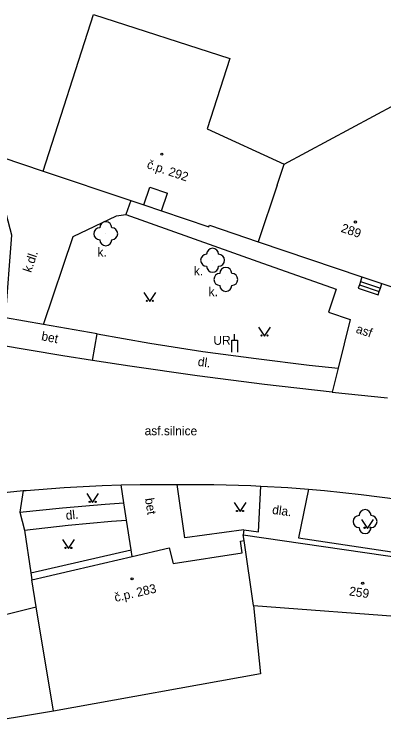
# Model space of a CAD drawing. Extents: x -544674 to -541478, y -1199076 to -1195527.
# Drawn here: x -542914.6 to -542883.7, y -1198202.9 to -1198142.3 of the extents above; entities that cross this region are included whole.
import ezdxf

# ---------------------------------------------------------------- set-up
doc = ezdxf.new("R2010")
doc.units = 0
for name, color, linetype in [('BUDOVY_MĚŘ', 7, 'Continuous'), ('BUDOVY_NEMĚŘ', 7, 'Continuous'), ('POMOC_POPIS', 7, 'Continuous'), ('ROZHRANÍ_PLOCH', 7, 'Continuous'), ('ZELEŇ', 7, 'Continuous'), ('ZN_BUDOV', 7, 'Continuous'), ('ZN_DOPLŇKOVÉ', 7, 'Continuous'), ('ZN_KULTUR', 7, 'Continuous'), ('Č_POPIS_ORIENT', 7, 'Continuous')]:
    doc.layers.add(name, color=color, linetype=linetype)

msp = doc.modelspace()

# ---------------------------------------------------------------- linework, layer by layer
at = {"layer": 'BUDOVY_MĚŘ'}
for points in [[(-542912.2, -1198155.37), (-542904.87, -1198157.84)], [(-542892.61, -1198156.55), (-542894.21, -1198161.29)], [(-542904.87, -1198157.84), (-542903.78, -1198158.21)], [(-542903.78, -1198158.21), (-542902.3, -1198158.71)], [(-542902.3, -1198158.71), (-542898.34, -1198160.05), (-542898.29, -1198159.91), (-542894.21, -1198161.29)], [(-542894.21, -1198161.29), (-542885.51, -1198164.23)], [(-542885.51, -1198164.23), (-542883.84, -1198164.79)], [(-542883.84, -1198164.79), (-542881.19, -1198165.68)], [(-542904.75, -1198187.64), (-542901.64, -1198186.92), (-542901.33, -1198188.23), (-542895.54, -1198187.34), (-542895.68, -1198186.36), (-542895.38, -1198186.32)], [(-542895.45, -1198185.83), (-542880.28, -1198188.03)], [(-542895.38, -1198186.32), (-542895.45, -1198185.83)], [(-542894.6, -1198191.76), (-542895.38, -1198186.32)], [(-542913.14, -1198189.59), (-542904.75, -1198187.64)], [(-542912.78, -1198191.87), (-542913.14, -1198189.59)], [(-542927.63, -1198193.04), (-542918.98, -1198191.04), (-542918.44, -1198193.25), (-542912.78, -1198191.87)]]:
    msp.add_lwpolyline(points, dxfattribs=at)
at = {"layer": 'BUDOVY_NEMĚŘ'}
for points in [[(-542912.2, -1198155.37), (-542908, -1198142.26), (-542896.58, -1198145.94), (-542898.48, -1198151.84), (-542892.02, -1198154.79)], [(-542892.61, -1198156.55), (-542892.02, -1198154.79), (-542882.67, -1198149.76)], [(-542894.6, -1198191.76), (-542894, -1198197.47), (-542911.34, -1198200.59), (-542912.78, -1198191.87)], [(-542894.6, -1198191.76), (-542881.22, -1198192.76)], [(-542911.34, -1198200.59), (-542925.16, -1198202.89), (-542927.63, -1198193.04)]]:
    msp.add_lwpolyline(points, dxfattribs=at)
at = {"layer": 'ROZHRANÍ_PLOCH'}
for points in [[(-542915.37, -1198167.65), (-542914.83, -1198160.74), (-542916.05, -1198156.17), (-542915.67, -1198154.2), (-542912.2, -1198155.37)], [(-542903.78, -1198158.21), (-542903.27, -1198156.72)], [(-542903.27, -1198156.72), (-542901.79, -1198157.22)], [(-542902.3, -1198158.71), (-542901.79, -1198157.22)], [(-542904.87, -1198157.84), (-542905.27, -1198159.02)], [(-542912.17, -1198168.22), (-542909.7, -1198160.84), (-542906.07, -1198159.12), (-542905.27, -1198159.02)], [(-542905.27, -1198159.02), (-542894.22, -1198162.94), (-542887.68, -1198165.27), (-542888.32, -1198167.18), (-542886.49, -1198167.79), (-542887.51, -1198171.87)], [(-542885.51, -1198164.23), (-542885.64, -1198164.62)], [(-542885.73, -1198164.9), (-542885.83, -1198165.19), (-542884.16, -1198165.75), (-542884.07, -1198165.47)], [(-542885.64, -1198164.62), (-542885.73, -1198164.9)], [(-542885.73, -1198164.9), (-542884.07, -1198165.47)], [(-542885.64, -1198164.62), (-542883.97, -1198165.18)], [(-542884.07, -1198165.47), (-542883.97, -1198165.18)], [(-542883.97, -1198165.18), (-542883.84, -1198164.79)], [(-542912.17, -1198168.22), (-542915.37, -1198167.65)], [(-542907.69, -1198169.01), (-542912.17, -1198168.22)], [(-542908.06, -1198171.24), (-542907.69, -1198169.01)], [(-542907.69, -1198169.01), (-542903.27, -1198169.78), (-542898.83, -1198170.47), (-542894.38, -1198171.08), (-542889.92, -1198171.62), (-542887.51, -1198171.87)], [(-542908.06, -1198171.24), (-542910.57, -1198170.85), (-542916.06, -1198169.91)], [(-542888.01, -1198173.88), (-542893.66, -1198173.24), (-542899.31, -1198172.52), (-542904.94, -1198171.72), (-542908.06, -1198171.24)], [(-542887.51, -1198171.87), (-542888.01, -1198173.88)], [(-542888.01, -1198173.88), (-542883.38, -1198174.36)], [(-542918.92, -1198182.7), (-542916.81, -1198182.43), (-542913.87, -1198182.13)], [(-542913.87, -1198182.13), (-542914.16, -1198183.94)], [(-542913.87, -1198182.13), (-542913.63, -1198182.11), (-542910.45, -1198181.86), (-542907.27, -1198181.7), (-542905.67, -1198181.66)], [(-542905.67, -1198181.66), (-542904.08, -1198181.62), (-542900.99, -1198181.61)], [(-542905.44, -1198183.16), (-542905.67, -1198181.66)], [(-542900.99, -1198181.61), (-542897.9, -1198181.62), (-542894.81, -1198181.71), (-542893.99, -1198181.75)], [(-542895.39, -1198185.41), (-542900.34, -1198186.09), (-542900.99, -1198181.61)], [(-542895.39, -1198185.41), (-542894.18, -1198185.59), (-542893.99, -1198181.75)], [(-542893.99, -1198181.75), (-542891.72, -1198181.88), (-542889.98, -1198182.02)], [(-542889.98, -1198182.02), (-542890.83, -1198186.09), (-542880.23, -1198187.67), (-542879.45, -1198183.34)], [(-542889.98, -1198182.02), (-542888.64, -1198182.12), (-542885.57, -1198182.45), (-542882.5, -1198182.86), (-542879.45, -1198183.34)], [(-542914.16, -1198183.94), (-542910.59, -1198183.56), (-542907.02, -1198183.27), (-542905.44, -1198183.16)], [(-542905.22, -1198184.6), (-542905.44, -1198183.16)], [(-542914.16, -1198183.94), (-542913.76, -1198185.45)], [(-542913.76, -1198185.45), (-542910.12, -1198185.03), (-542906.47, -1198184.7), (-542905.22, -1198184.6)], [(-542904.84, -1198187.08), (-542905.22, -1198184.6)], [(-542913.76, -1198185.45), (-542913.23, -1198189.02)], [(-542895.39, -1198185.41), (-542895.45, -1198185.83)], [(-542913.23, -1198189.02), (-542904.84, -1198187.08)], [(-542904.75, -1198187.64), (-542904.84, -1198187.08)], [(-542913.23, -1198189.02), (-542913.14, -1198189.59)]]:
    msp.add_lwpolyline(points, dxfattribs=at)
at = {"layer": 'ZELEŇ'}
for centre in [(-542906.96, -1198160.62), (-542898.02, -1198162.84), (-542896.91, -1198164.45), (-542885.25, -1198184.72)]:
    msp.add_circle(centre, 0.0005, dxfattribs=at)
for centre, start, end in [((-542906.96, -1198160.12), 0, 179.99999), ((-542907.46, -1198160.62), 89.99999, 269.99999), ((-542906.46, -1198160.62), 270, 89.99999), ((-542906.96, -1198161.12), 179.99999, 359.99999), ((-542898.02, -1198162.34), 0, 179.99999), ((-542898.52, -1198162.84), 89.99999, 269.99999), ((-542897.52, -1198162.84), 270, 89.99999), ((-542898.02, -1198163.34), 179.99999, 359.99999), ((-542897.41, -1198164.45), 89.99999, 269.99999), ((-542896.91, -1198163.95), 0, 179.99999), ((-542896.41, -1198164.45), 270, 89.99999), ((-542896.91, -1198164.95), 179.99999, 359.99999), ((-542885.25, -1198184.22), 0, 179.99999), ((-542885.75, -1198184.72), 89.99999, 269.99999), ((-542884.75, -1198184.72), 270, 89.99999), ((-542885.25, -1198185.22), 179.99999, 359.99999)]:
    msp.add_arc(centre, 0.5, start, end, dxfattribs=at)
at = {"layer": 'ZN_BUDOV'}
for centre in [(-542902.27, -1198153.95), (-542886.06, -1198159.64), (-542904.76, -1198189.52), (-542885.45, -1198189.89)]:
    msp.add_circle(centre, 0.0875, dxfattribs=at)
at = {"layer": 'ZN_DOPLŇKOVÉ'}
msp.add_line((-542896.17, -1198169.54), (-542896.17, -1198169.04), dxfattribs=at)
msp.add_lwpolyline([(-542896.42, -1198170.54), (-542896.42, -1198169.54), (-542895.92, -1198169.54), (-542895.92, -1198170.54)], dxfattribs=at)
at = {"layer": 'ZN_KULTUR'}
for points in [[(-542903.77, -1198165.54), (-542903.27, -1198166.29), (-542902.77, -1198165.54)], [(-542894.17, -1198168.44), (-542893.67, -1198169.19), (-542893.17, -1198168.44)], [(-542908.56, -1198182.37), (-542908.06, -1198183.12), (-542907.56, -1198182.37)], [(-542896.22, -1198183.14), (-542895.72, -1198183.89), (-542895.22, -1198183.14)], [(-542885.54, -1198184.54), (-542885.04, -1198185.29), (-542884.54, -1198184.54)], [(-542910.59, -1198186.23), (-542910.09, -1198186.98), (-542909.59, -1198186.23)]]:
    msp.add_lwpolyline(points, dxfattribs=at)
for centre in [(-542903.52, -1198166.24), (-542903.02, -1198166.24), (-542893.92, -1198169.14), (-542893.42, -1198169.14), (-542908.31, -1198183.07), (-542907.81, -1198183.07), (-542895.97, -1198183.84), (-542895.47, -1198183.84), (-542885.29, -1198185.24), (-542884.79, -1198185.24), (-542910.34, -1198186.93), (-542909.84, -1198186.93)]:
    msp.add_circle(centre, 0.05, dxfattribs=at)

# ---------------------------------------------------------------- texts
at = {"layer": 'POMOC_POPIS'}
for s, rotation, p in [('k.dl.', 71.49521, (-542913.21, -1198163.92)), ('bet', 349.03002, (-542912.4, -1198169.53)), ('asf', 341.36, (-542886.07, -1198168.89)), ('dl.', 352.37999, (-542899.29, -1198171.68)), ('asf.silnice', 359.81458, (-542903.71, -1198177.49)), ('bet', 278.68999, (-542903.68, -1198182.8)), ('dla.', 352.69001, (-542893.06, -1198184.08)), ('dl.', 5.34999, (-542910.28, -1198184.58))]:
    msp.add_text(s, height=0.75, rotation=rotation, dxfattribs=at).set_placement(p)
msp.add_text('UR', height=0.75, dxfattribs=at).set_placement((-542897.95, -1198169.92))
at = {"layer": 'ZELEŇ'}
for p in [(-542907.66, -1198162.53), (-542899.59, -1198164.1), (-542898.35, -1198165.85)]:
    msp.add_text('k.', height=0.75, dxfattribs=at).set_placement(p)
at = {"layer": 'Č_POPIS_ORIENT'}
for s, rotation, p in [('č.p. 292', 341.34001, (-542903.58, -1198155.11)), ('289', 341.36, (-542887.32, -1198160.45)), ('č.p. 283', 13.08, (-542906.15, -1198191.46)), ('259', 351.75999, (-542886.62, -1198190.9))]:
    msp.add_text(s, height=0.75, rotation=rotation, dxfattribs=at).set_placement(p)

doc.saveas('drawing.dxf')
